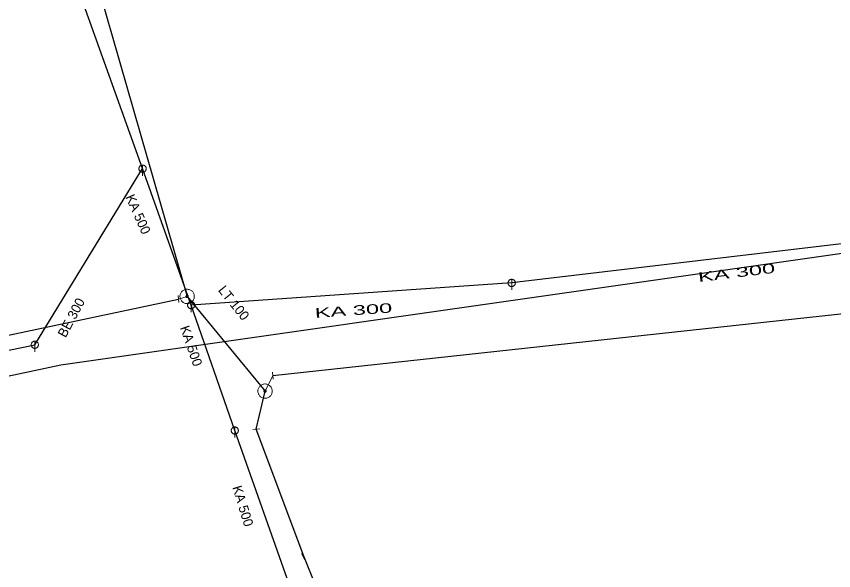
# Model space of a CAD drawing. Extents: x -687515 to -686506, y -974029 to -973461.
# Drawn here: x -687119.3 to -687062.3, y -973591.6 to -973553 of the extents above; entities that cross this region are included whole.
import ezdxf
from ezdxf.enums import TextEntityAlignment as Align

# ---------------------------------------------------------------- set-up
doc = ezdxf.new("R2010")
doc.units = 0
doc.header["$LTSCALE"] = 0.27
for name, color, linetype, lineweight in [('1', 7, 'Continuous', 13), ('14', 7, 'Continuous', 25), ('17', 7, 'Continuous', 25), ('22', 7, 'Continuous', 13), ('34', 7, 'Continuous', 13), ('47', 7, 'Continuous', 13)]:
    doc.layers.add(name, color=color, linetype=linetype, lineweight=lineweight)

msp = doc.modelspace()

# ---------------------------------------------------------------- linework, layer by layer
at = {"layer": '14'}
for p, q in [((-687118.01, -973575.901), (-687110.498, -973563.624)), ((-687053.62, -973567.9), (-687084.75, -973571.59)), ((-687084.75, -973571.59), (-687107.11, -973573.14)), ((-687154.803, -973583.4), (-687118.01, -973575.901)), ((-687099.365, -973595.104), (-687104.065, -973581.877))]:
    msp.add_line(p, q, dxfattribs=at)
at = {"layer": '14', "lineweight": 13}
for p, q in [((-687107.989, -973572.719), (-687107.388, -973572.532)), ((-687101.409, -973578.049), (-687101.954, -973579.133)), ((-687099.26, -973590.649), (-687099.299, -973590.672))]:
    msp.add_line(p, q, dxfattribs=at)
at = {"layer": '14'}
for points in [[(-687110.498, -973563.624), (-687122.706, -973529.611), (-687136.829, -973490.92)], [(-687104.065, -973581.877), (-687107.109, -973573.14), (-687110.498, -973563.624)]]:
    msp.add_lwpolyline(points, dxfattribs=at)
at = {"layer": '17'}
for p, q in [((-687101.409, -973578.049), (-686980.567, -973564.875)), ((-687148.873, -973581.4), (-687107.989, -973572.719))]:
    msp.add_line(p, q, dxfattribs=at)
for points in [[(-686645.309, -973464.46), (-686646.34, -973464.75), (-686680.188, -973471.317), (-686771.188, -973470.317), (-686761.188, -973557.317), (-686894.188, -973571.317), (-686953.188, -973578.317), (-686955.188, -973554.317), (-687116.188, -973577.317), (-687229.188, -973601.317), (-687468.188, -973649.317), (-687458.188, -973700.317)], [(-687118.206, -973534.968), (-687107.388, -973572.532), (-687101.954, -973579.133)], [(-687087.478, -973622.912), (-687089.426, -973617.563), (-687098.39, -973592.77), (-687099.26, -973590.649), (-687102.57, -973581.78), (-687101.954, -973579.133)]]:
    msp.add_lwpolyline(points, dxfattribs=at)
at = {"layer": '22'}
for p, q in [((-687110.497, -973563.372), (-687110.498, -973564.115)), ((-687084.749, -973571.338), (-687084.75, -973572.081)), ((-687107.109, -973572.888), (-687107.11, -973573.632)), ((-687118.009, -973575.649), (-687118.01, -973576.392)), ((-687104.064, -973581.625), (-687104.065, -973582.369))]:
    msp.add_line(p, q, dxfattribs=at)
for points in [[(-687110.246, -973563.624), (-687110.247, -973563.598), (-687110.251, -973563.572), (-687110.257, -973563.546), (-687110.267, -973563.522), (-687110.279, -973563.498), (-687110.293, -973563.476), (-687110.31, -973563.455), (-687110.328, -973563.437), (-687110.349, -973563.42), (-687110.371, -973563.406), (-687110.395, -973563.394), (-687110.419, -973563.384), (-687110.445, -973563.378), (-687110.471, -973563.374), (-687110.497, -973563.372), (-687110.523, -973563.373), (-687110.549, -973563.377), (-687110.575, -973563.383), (-687110.6, -973563.393), (-687110.623, -973563.405), (-687110.645, -973563.419), (-687110.666, -973563.436), (-687110.684, -973563.454), (-687110.701, -973563.475), (-687110.715, -973563.497), (-687110.727, -973563.521), (-687110.737, -973563.545), (-687110.744, -973563.571), (-687110.748, -973563.597), (-687110.75, -973563.623), (-687110.749, -973563.649), (-687110.745, -973563.675), (-687110.738, -973563.701), (-687110.728, -973563.726), (-687110.716, -973563.749), (-687110.702, -973563.771), (-687110.685, -973563.792), (-687110.667, -973563.81), (-687110.646, -973563.827), (-687110.624, -973563.841), (-687110.601, -973563.853), (-687110.576, -973563.863), (-687110.55, -973563.87), (-687110.524, -973563.874), (-687110.498, -973563.875), (-687110.472, -973563.875), (-687110.446, -973563.871), (-687110.42, -973563.864), (-687110.396, -973563.854), (-687110.372, -973563.842), (-687110.35, -973563.828), (-687110.329, -973563.811), (-687110.311, -973563.793), (-687110.294, -973563.772), (-687110.28, -973563.75), (-687110.268, -973563.727), (-687110.258, -973563.702), (-687110.252, -973563.676), (-687110.248, -973563.65)], [(-687084.498, -973571.59), (-687084.499, -973571.564), (-687084.503, -973571.538), (-687084.509, -973571.512), (-687084.519, -973571.488), (-687084.531, -973571.464), (-687084.545, -973571.442), (-687084.562, -973571.421), (-687084.58, -973571.403), (-687084.601, -973571.386), (-687084.623, -973571.372), (-687084.647, -973571.36), (-687084.671, -973571.35), (-687084.697, -973571.344), (-687084.723, -973571.34), (-687084.749, -973571.338), (-687084.775, -973571.339), (-687084.801, -973571.343), (-687084.827, -973571.349), (-687084.852, -973571.359), (-687084.875, -973571.371), (-687084.897, -973571.385), (-687084.918, -973571.402), (-687084.936, -973571.42), (-687084.953, -973571.441), (-687084.967, -973571.463), (-687084.979, -973571.487), (-687084.989, -973571.511), (-687084.996, -973571.537), (-687085, -973571.563), (-687085.002, -973571.589), (-687085.001, -973571.615), (-687084.997, -973571.641), (-687084.99, -973571.667), (-687084.98, -973571.692), (-687084.968, -973571.715), (-687084.954, -973571.737), (-687084.937, -973571.758), (-687084.919, -973571.776), (-687084.898, -973571.793), (-687084.876, -973571.807), (-687084.853, -973571.819), (-687084.828, -973571.829), (-687084.802, -973571.836), (-687084.776, -973571.84), (-687084.75, -973571.842), (-687084.724, -973571.841), (-687084.698, -973571.837), (-687084.672, -973571.83), (-687084.648, -973571.82), (-687084.624, -973571.808), (-687084.602, -973571.794), (-687084.581, -973571.777), (-687084.563, -973571.759), (-687084.546, -973571.738), (-687084.532, -973571.716), (-687084.52, -973571.693), (-687084.51, -973571.668), (-687084.504, -973571.642), (-687084.5, -973571.616)], [(-687106.858, -973573.14), (-687106.859, -973573.114), (-687106.863, -973573.088), (-687106.869, -973573.062), (-687106.879, -973573.038), (-687106.891, -973573.014), (-687106.905, -973572.992), (-687106.922, -973572.971), (-687106.94, -973572.953), (-687106.961, -973572.936), (-687106.983, -973572.922), (-687107.007, -973572.91), (-687107.031, -973572.9), (-687107.057, -973572.894), (-687107.083, -973572.89), (-687107.109, -973572.888), (-687107.135, -973572.889), (-687107.161, -973572.893), (-687107.187, -973572.899), (-687107.212, -973572.909), (-687107.235, -973572.921), (-687107.257, -973572.935), (-687107.278, -973572.952), (-687107.296, -973572.97), (-687107.313, -973572.991), (-687107.327, -973573.013), (-687107.339, -973573.037), (-687107.349, -973573.061), (-687107.356, -973573.087), (-687107.36, -973573.113), (-687107.362, -973573.139), (-687107.361, -973573.165), (-687107.357, -973573.191), (-687107.35, -973573.217), (-687107.34, -973573.242), (-687107.328, -973573.265), (-687107.314, -973573.287), (-687107.297, -973573.308), (-687107.279, -973573.326), (-687107.258, -973573.343), (-687107.236, -973573.357), (-687107.213, -973573.369), (-687107.188, -973573.379), (-687107.162, -973573.386), (-687107.136, -973573.39), (-687107.11, -973573.392), (-687107.084, -973573.391), (-687107.058, -973573.387), (-687107.032, -973573.38), (-687107.008, -973573.37), (-687106.984, -973573.358), (-687106.962, -973573.344), (-687106.941, -973573.327), (-687106.923, -973573.309), (-687106.906, -973573.288), (-687106.892, -973573.266), (-687106.88, -973573.243), (-687106.87, -973573.218), (-687106.864, -973573.192), (-687106.86, -973573.166)], [(-687117.758, -973575.901), (-687117.759, -973575.875), (-687117.763, -973575.849), (-687117.769, -973575.823), (-687117.779, -973575.799), (-687117.791, -973575.775), (-687117.805, -973575.753), (-687117.822, -973575.732), (-687117.84, -973575.714), (-687117.861, -973575.697), (-687117.883, -973575.683), (-687117.907, -973575.671), (-687117.931, -973575.661), (-687117.957, -973575.655), (-687117.983, -973575.651), (-687118.009, -973575.649), (-687118.035, -973575.65), (-687118.061, -973575.654), (-687118.087, -973575.66), (-687118.112, -973575.67), (-687118.135, -973575.682), (-687118.157, -973575.696), (-687118.178, -973575.713), (-687118.196, -973575.731), (-687118.213, -973575.752), (-687118.227, -973575.774), (-687118.239, -973575.798), (-687118.249, -973575.822), (-687118.256, -973575.848), (-687118.26, -973575.874), (-687118.262, -973575.9), (-687118.261, -973575.926), (-687118.257, -973575.952), (-687118.25, -973575.978), (-687118.24, -973576.003), (-687118.228, -973576.026), (-687118.214, -973576.048), (-687118.197, -973576.069), (-687118.179, -973576.087), (-687118.158, -973576.104), (-687118.136, -973576.118), (-687118.113, -973576.13), (-687118.088, -973576.14), (-687118.062, -973576.147), (-687118.036, -973576.151), (-687118.01, -973576.152), (-687117.984, -973576.152), (-687117.958, -973576.148), (-687117.932, -973576.141), (-687117.908, -973576.131), (-687117.884, -973576.119), (-687117.862, -973576.105), (-687117.841, -973576.088), (-687117.823, -973576.07), (-687117.806, -973576.049), (-687117.792, -973576.027), (-687117.78, -973576.004), (-687117.77, -973575.979), (-687117.764, -973575.953), (-687117.76, -973575.927)], [(-687103.813, -973581.877), (-687103.814, -973581.851), (-687103.818, -973581.825), (-687103.824, -973581.799), (-687103.834, -973581.775), (-687103.846, -973581.751), (-687103.86, -973581.729), (-687103.877, -973581.708), (-687103.895, -973581.69), (-687103.916, -973581.673), (-687103.938, -973581.659), (-687103.962, -973581.647), (-687103.986, -973581.637), (-687104.012, -973581.631), (-687104.038, -973581.627), (-687104.064, -973581.625), (-687104.09, -973581.626), (-687104.116, -973581.63), (-687104.142, -973581.636), (-687104.167, -973581.646), (-687104.19, -973581.658), (-687104.212, -973581.672), (-687104.233, -973581.689), (-687104.251, -973581.707), (-687104.268, -973581.728), (-687104.282, -973581.75), (-687104.294, -973581.774), (-687104.304, -973581.798), (-687104.311, -973581.824), (-687104.315, -973581.85), (-687104.316, -973581.876), (-687104.316, -973581.902), (-687104.312, -973581.928), (-687104.305, -973581.954), (-687104.295, -973581.979), (-687104.283, -973582.002), (-687104.269, -973582.024), (-687104.252, -973582.045), (-687104.234, -973582.063), (-687104.213, -973582.08), (-687104.191, -973582.094), (-687104.168, -973582.106), (-687104.143, -973582.116), (-687104.117, -973582.123), (-687104.091, -973582.127), (-687104.065, -973582.129), (-687104.039, -973582.128), (-687104.013, -973582.124), (-687103.987, -973582.117), (-687103.963, -973582.107), (-687103.939, -973582.095), (-687103.917, -973582.081), (-687103.896, -973582.064), (-687103.878, -973582.046), (-687103.861, -973582.025), (-687103.847, -973582.003), (-687103.835, -973581.98), (-687103.825, -973581.955), (-687103.819, -973581.929), (-687103.815, -973581.903)]]:
    msp.add_lwpolyline(points, close=True, dxfattribs=at)
at = {"layer": '34'}
for p, q in [((-687107.964, -973572.965), (-687108.013, -973572.472)), ((-687101.384, -973578.295), (-687101.433, -973577.802)), ((-687102.323, -973581.755), (-687102.816, -973581.804)), ((-687099.419, -973590.455), (-687099.178, -973590.888))]:
    msp.add_line(p, q, dxfattribs=at)
at = {"layer": '47'}
for points in [[(-687107.21, -973572.999), (-687107.162, -973572.978), (-687107.117, -973572.952), (-687107.075, -973572.921), (-687107.036, -973572.887), (-687107, -973572.848), (-687106.969, -973572.805), (-687106.944, -973572.76), (-687106.922, -973572.712), (-687106.905, -973572.663), (-687106.894, -973572.612), (-687106.888, -973572.559), (-687106.889, -973572.507), (-687106.893, -973572.455), (-687106.904, -973572.404), (-687106.92, -973572.354), (-687106.941, -973572.306), (-687106.967, -973572.261), (-687106.998, -973572.218), (-687107.032, -973572.18), (-687107.071, -973572.144), (-687107.114, -973572.113), (-687107.16, -973572.087), (-687107.207, -973572.065), (-687107.256, -973572.049), (-687107.307, -973572.038), (-687107.36, -973572.032), (-687107.412, -973572.032), (-687107.464, -973572.037), (-687107.515, -973572.048), (-687107.565, -973572.064), (-687107.613, -973572.085), (-687107.658, -973572.111), (-687107.701, -973572.141), (-687107.739, -973572.176), (-687107.775, -973572.215), (-687107.806, -973572.257), (-687107.833, -973572.303), (-687107.854, -973572.35), (-687107.87, -973572.4), (-687107.881, -973572.451), (-687107.887, -973572.504), (-687107.888, -973572.556), (-687107.882, -973572.608), (-687107.871, -973572.659), (-687107.855, -973572.709), (-687107.834, -973572.757), (-687107.808, -973572.802), (-687107.778, -973572.844), (-687107.743, -973572.883), (-687107.704, -973572.919), (-687107.662, -973572.95), (-687107.617, -973572.976), (-687107.569, -973572.997), (-687107.519, -973573.014), (-687107.468, -973573.025), (-687107.415, -973573.031), (-687107.364, -973573.031), (-687107.311, -973573.026), (-687107.26, -973573.015)], [(-687107.358, -973572.608), (-687107.35, -973572.605), (-687107.343, -973572.6), (-687107.336, -973572.596), (-687107.33, -973572.59), (-687107.324, -973572.583), (-687107.319, -973572.576), (-687107.314, -973572.569), (-687107.311, -973572.561), (-687107.309, -973572.553), (-687107.307, -973572.545), (-687107.306, -973572.536), (-687107.306, -973572.527), (-687107.307, -973572.519), (-687107.308, -973572.511), (-687107.311, -973572.502), (-687107.314, -973572.494), (-687107.319, -973572.487), (-687107.323, -973572.48), (-687107.329, -973572.474), (-687107.336, -973572.468), (-687107.343, -973572.463), (-687107.35, -973572.458), (-687107.358, -973572.455), (-687107.366, -973572.452), (-687107.374, -973572.451), (-687107.383, -973572.45), (-687107.392, -973572.45), (-687107.4, -973572.451), (-687107.408, -973572.452), (-687107.417, -973572.455), (-687107.425, -973572.458), (-687107.432, -973572.463), (-687107.439, -973572.467), (-687107.445, -973572.473), (-687107.451, -973572.48), (-687107.456, -973572.486), (-687107.461, -973572.494), (-687107.464, -973572.502), (-687107.467, -973572.51), (-687107.468, -973572.518), (-687107.469, -973572.527), (-687107.469, -973572.536), (-687107.468, -973572.544), (-687107.467, -973572.552), (-687107.464, -973572.561), (-687107.461, -973572.569), (-687107.456, -973572.576), (-687107.452, -973572.583), (-687107.446, -973572.589), (-687107.439, -973572.595), (-687107.433, -973572.6), (-687107.425, -973572.605), (-687107.417, -973572.608), (-687107.409, -973572.61), (-687107.401, -973572.612), (-687107.392, -973572.613), (-687107.383, -973572.613), (-687107.375, -973572.612), (-687107.367, -973572.611)], [(-687101.776, -973579.6), (-687101.728, -973579.579), (-687101.683, -973579.553), (-687101.641, -973579.522), (-687101.602, -973579.488), (-687101.566, -973579.449), (-687101.535, -973579.406), (-687101.51, -973579.361), (-687101.488, -973579.313), (-687101.471, -973579.264), (-687101.46, -973579.213), (-687101.454, -973579.16), (-687101.455, -973579.108), (-687101.459, -973579.056), (-687101.47, -973579.005), (-687101.486, -973578.955), (-687101.507, -973578.907), (-687101.533, -973578.862), (-687101.564, -973578.819), (-687101.598, -973578.781), (-687101.637, -973578.745), (-687101.68, -973578.714), (-687101.726, -973578.688), (-687101.773, -973578.666), (-687101.822, -973578.65), (-687101.873, -973578.639), (-687101.926, -973578.633), (-687101.978, -973578.633), (-687102.03, -973578.638), (-687102.081, -973578.649), (-687102.131, -973578.665), (-687102.179, -973578.686), (-687102.224, -973578.712), (-687102.267, -973578.742), (-687102.305, -973578.777), (-687102.341, -973578.816), (-687102.372, -973578.858), (-687102.399, -973578.904), (-687102.42, -973578.951), (-687102.436, -973579.001), (-687102.447, -973579.052), (-687102.453, -973579.105), (-687102.454, -973579.157), (-687102.448, -973579.209), (-687102.437, -973579.26), (-687102.421, -973579.31), (-687102.4, -973579.358), (-687102.374, -973579.403), (-687102.344, -973579.445), (-687102.309, -973579.484), (-687102.27, -973579.52), (-687102.228, -973579.551), (-687102.183, -973579.577), (-687102.135, -973579.598), (-687102.085, -973579.615), (-687102.034, -973579.626), (-687101.981, -973579.632), (-687101.93, -973579.632), (-687101.877, -973579.627), (-687101.826, -973579.616)], [(-687101.924, -973579.209), (-687101.916, -973579.206), (-687101.909, -973579.201), (-687101.902, -973579.197), (-687101.896, -973579.191), (-687101.89, -973579.184), (-687101.885, -973579.177), (-687101.88, -973579.17), (-687101.877, -973579.162), (-687101.875, -973579.154), (-687101.873, -973579.146), (-687101.872, -973579.137), (-687101.872, -973579.128), (-687101.873, -973579.12), (-687101.874, -973579.112), (-687101.877, -973579.103), (-687101.88, -973579.095), (-687101.885, -973579.088), (-687101.889, -973579.081), (-687101.895, -973579.075), (-687101.902, -973579.069), (-687101.909, -973579.064), (-687101.916, -973579.059), (-687101.924, -973579.056), (-687101.932, -973579.053), (-687101.94, -973579.052), (-687101.949, -973579.051), (-687101.958, -973579.051), (-687101.966, -973579.052), (-687101.974, -973579.053), (-687101.983, -973579.056), (-687101.991, -973579.059), (-687101.998, -973579.064), (-687102.005, -973579.068), (-687102.011, -973579.074), (-687102.017, -973579.081), (-687102.022, -973579.087), (-687102.027, -973579.095), (-687102.03, -973579.103), (-687102.033, -973579.111), (-687102.034, -973579.119), (-687102.035, -973579.128), (-687102.035, -973579.137), (-687102.034, -973579.145), (-687102.033, -973579.153), (-687102.03, -973579.162), (-687102.027, -973579.17), (-687102.022, -973579.177), (-687102.018, -973579.184), (-687102.012, -973579.19), (-687102.005, -973579.196), (-687101.999, -973579.201), (-687101.991, -973579.206), (-687101.983, -973579.209), (-687101.975, -973579.211), (-687101.967, -973579.213), (-687101.958, -973579.214), (-687101.949, -973579.214), (-687101.941, -973579.213), (-687101.933, -973579.212)]]:
    msp.add_lwpolyline(points, close=True, dxfattribs=at)

# ---------------------------------------------------------------- texts
at = {"layer": '1'}
for s, rotation, p in [('KA 500', 294, (-687111.11, -973566.934)), ('LT 100', 309, (-687104.39, -973573.19)), ('BE 300', 62, (-687115.177, -973574.166)), ('KA 500', 289, (-687107.415, -973576.088)), ('KA 500', 287, (-687103.815, -973587.235))]:
    msp.add_text(s, height=0.6667, rotation=rotation, dxfattribs=at).set_placement(p, align=Align.CENTER)
at = {"layer": '1', "width": 1.85}
for rotation, p in [(7, (-687069.031, -973571.205)), (4, (-687095.765, -973573.838))]:
    msp.add_text('KA 300', height=0.6667, rotation=rotation, dxfattribs=at).set_placement(p, align=Align.CENTER)

doc.saveas('drawing.dxf')
